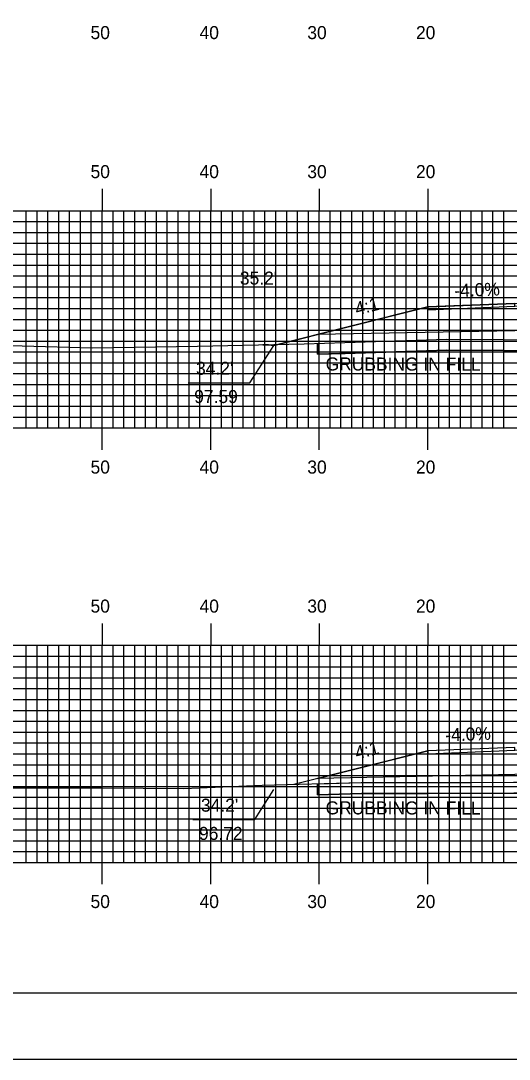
# Model space of a CAD drawing. Extents: x 1778712 to 1779055, y 442591 to 442811.
# Drawn here: x 1778820.3 to 1778865.3, y 442590.5 to 442686.2 of the extents above; entities that cross this region are included whole.
import ezdxf

# ---------------------------------------------------------------- set-up
doc = ezdxf.new("R2010")
doc.units = 0
for name, color, linetype in [('ANNOTATION', 7, 'Continuous'), ('BORDER', 7, 'Continuous'), ('D_Roadway_Centerline', 7, 'Continuous'), ('D_Roadway_Edge_Shoulder', 7, 'Continuous'), ('D_Roadway_SlopeLines', 7, 'Continuous'), ('D_Roadway_SubGrade', 7, 'Continuous'), ('D_Text_Standard', 7, 'Continuous'), ('GRUBBING IN FILL', 7, 'Continuous'), ('H_V ANNOTATION', 7, 'Continuous'), ('MAJOR', 7, 'Continuous'), ('MINOR', 7, 'Continuous'), ('PLOT BOUNDARY', 7, 'Continuous'), ('S_Roadway_Centerline', 7, 'Continuous')]:
    doc.layers.add(name, color=color, linetype=linetype)

msp = doc.modelspace()

# ---------------------------------------------------------------- linework, layer by layer
at = {"layer": 'ANNOTATION'}
for points in [[(1778835.728, 442652.833), (1778841.42, 442652.833), (1778843.642, 442656.259)], [(1778836.183, 442612.611), (1778841.875, 442612.611), (1778843.616, 442615.385)]]:
    msp.add_lwpolyline(points, dxfattribs=at)
at = {"layer": 'BORDER'}
msp.add_lwpolyline([(1778728.216, 442596.665), (1779048.216, 442596.665), (1779048.216, 442806.665), (1778728.216, 442806.665)], close=True, dxfattribs=at)
at = {"layer": 'D_Roadway_Centerline'}
msp.add_lwpolyline([(1778842.631, 442656.331), (1778842.722, 442656.331), (1778842.883, 442656.331), (1778843.136, 442656.319), (1778843.376, 442656.296), (1778843.389, 442656.295), (1778843.41, 442656.292), (1778843.642, 442656.259), (1778846.32, 442656.929), (1778847.642, 442657.259), (1778857.816, 442659.802), (1778859.485, 442659.869), (1778865.816, 442660.122), (1778877.816, 442660.362), (1778881.804, 442660.282), (1778889.816, 442660.122), (1778903.149, 442659.589), (1778912.858, 442657.162), (1778916.47, 442656.259)], dxfattribs=at)
at = {"layer": 'D_Roadway_Edge_Shoulder'}
for points in [[(1778865.816, 442660.122), (1778857.816, 442659.802), (1778857.816, 442659.552), (1778865.816, 442659.872)], [(1778865.816, 442619.247), (1778857.816, 442618.927), (1778857.816, 442618.677), (1778865.816, 442618.997)]]:
    msp.add_lwpolyline(points, close=True, dxfattribs=at)
at = {"layer": 'D_Roadway_SlopeLines'}
for points in [[(1778857.816, 442659.802), (1778843.642, 442656.259)], [(1778843.642, 442656.259), (1778843.389, 442656.295), (1778843.136, 442656.319), (1778842.883, 442656.331), (1778842.631, 442656.331)], [(1778857.816, 442618.927), (1778845.478, 442615.843)]]:
    msp.add_lwpolyline(points, dxfattribs=at)
at = {"layer": 'D_Roadway_SubGrade'}
for points in [[(1778865.816, 442657.622), (1778847.642, 442657.259), (1778857.816, 442659.802), (1778857.816, 442659.552), (1778865.816, 442659.872), (1778877.816, 442660.112), (1778889.816, 442659.872), (1778903.149, 442659.339), (1778903.149, 442659.589), (1778912.858, 442657.162), (1778889.816, 442657.622), (1778877.816, 442657.862)], [(1778865.816, 442616.747), (1778847.642, 442616.384), (1778857.816, 442618.927), (1778857.816, 442618.677), (1778865.816, 442618.997), (1778877.816, 442619.237), (1778889.816, 442618.997), (1778899.816, 442618.597), (1778899.816, 442618.847), (1778909.815, 442616.348), (1778889.816, 442616.747), (1778877.816, 442616.987)]]:
    msp.add_lwpolyline(points, close=True, dxfattribs=at)
at = {"layer": 'GRUBBING IN FILL'}
for p, q in [((1778847.642, 442656.456), (1778847.642, 442655.456)), ((1778847.642, 442656.456), (1778847.642, 442655.456)), ((1778847.642, 442615.902), (1778847.642, 442614.901)), ((1778847.642, 442615.902), (1778847.642, 442614.901))]:
    msp.add_line(p, q, dxfattribs=at)
for points in [[(1778847.642, 442656.456), (1778848.306, 442656.475), (1778850.185, 442656.529), (1778854.875, 442656.682), (1778859.566, 442656.834), (1778864.784, 442656.8), (1778870.002, 442656.765), (1778872.983, 442656.777), (1778877.816, 442656.845), (1778877.816, 442655.845), (1778872.992, 442655.777), (1778870.001, 442655.765), (1778864.79, 442655.8), (1778859.579, 442655.834), (1778854.897, 442655.682), (1778847.642, 442655.456)], [(1778847.642, 442656.456), (1778848.306, 442656.475), (1778850.185, 442656.529), (1778854.875, 442656.682), (1778859.566, 442656.834), (1778864.784, 442656.8), (1778870.002, 442656.765), (1778872.983, 442656.777), (1778877.816, 442656.845), (1778877.816, 442655.845), (1778872.992, 442655.777), (1778870.001, 442655.765), (1778864.79, 442655.8), (1778859.579, 442655.834), (1778854.897, 442655.682), (1778847.642, 442655.456)], [(1778847.642, 442614.901), (1778847.642, 442615.902), (1778851.685, 442616.011), (1778854.763, 442616.015), (1778861.781, 442616.033), (1778868.104, 442616.05), (1778874.6, 442616.221), (1778877.816, 442616.334), (1778877.816, 442615.333), (1778874.638, 442615.222), (1778870.508, 442615.053), (1778865.724, 442615.048), (1778857.843, 442615.018), (1778851.699, 442615.011)], [(1778847.642, 442614.901), (1778847.642, 442615.902), (1778851.685, 442616.011), (1778854.763, 442616.015), (1778861.781, 442616.033), (1778868.104, 442616.05), (1778874.6, 442616.221), (1778877.816, 442616.334), (1778877.816, 442615.333), (1778874.638, 442615.222), (1778870.508, 442615.053), (1778865.724, 442615.048), (1778857.843, 442615.018), (1778851.699, 442615.011)]]:
    msp.add_lwpolyline(points, close=True, dxfattribs=at)
for points in [[(1778847.642, 442655.456), (1778850.215, 442655.53), (1778859.579, 442655.834), (1778870.001, 442655.765), (1778872.992, 442655.777), (1778882.925, 442655.917), (1778895.028, 442656.037), (1778895.082, 442656.036), (1778895.146, 442656.035), (1778906.02, 442655.886), (1778907.99, 442655.97)], [(1778847.642, 442655.456), (1778850.215, 442655.53), (1778859.579, 442655.834), (1778870.001, 442655.765), (1778872.992, 442655.777), (1778882.925, 442655.917), (1778895.028, 442656.037), (1778895.082, 442656.036), (1778895.146, 442656.035), (1778906.02, 442655.886), (1778907.99, 442655.97)], [(1778847.642, 442614.901), (1778851.699, 442615.011), (1778857.843, 442615.018), (1778865.724, 442615.048), (1778870.508, 442615.053), (1778874.638, 442615.222), (1778882.441, 442615.495), (1778890.211, 442615.311), (1778897.213, 442615.21), (1778905.126, 442615.323), (1778907.99, 442615.371)], [(1778847.642, 442614.901), (1778851.699, 442615.011), (1778857.843, 442615.018), (1778865.724, 442615.048), (1778870.508, 442615.053), (1778874.638, 442615.222), (1778882.441, 442615.495), (1778890.211, 442615.311), (1778897.213, 442615.21), (1778905.126, 442615.323), (1778907.99, 442615.371)]]:
    msp.add_lwpolyline(points, dxfattribs=at)
at = {"layer": 'MAJOR'}
for p, q in [((1778827.816, 442670.669), (1778827.816, 442668.665)), ((1778837.816, 442670.669), (1778837.816, 442668.665)), ((1778847.816, 442670.669), (1778847.816, 442668.665)), ((1778857.816, 442670.669), (1778857.816, 442668.665)), ((1778737.816, 442668.665), (1779017.816, 442668.665)), ((1778737.816, 442668.665), (1779017.816, 442668.665)), ((1778827.816, 442648.665), (1778827.816, 442668.665)), ((1778837.816, 442648.665), (1778837.816, 442668.665)), ((1778847.816, 442648.665), (1778847.816, 442668.665)), ((1778857.816, 442648.665), (1778857.816, 442668.665)), ((1778737.816, 442663.665), (1779017.816, 442663.665)), ((1778737.816, 442658.665), (1779017.816, 442658.665)), ((1778737.816, 442653.665), (1779017.816, 442653.665)), ((1778737.816, 442648.665), (1779017.816, 442648.665)), ((1778737.816, 442648.665), (1779017.816, 442648.665)), ((1778827.816, 442646.661), (1778827.816, 442648.665)), ((1778837.816, 442646.661), (1778837.816, 442648.665)), ((1778847.816, 442646.661), (1778847.816, 442648.665)), ((1778857.816, 442646.661), (1778857.816, 442648.665)), ((1778827.816, 442630.669), (1778827.816, 442628.665)), ((1778837.816, 442630.669), (1778837.816, 442628.665)), ((1778847.816, 442630.669), (1778847.816, 442628.665)), ((1778857.816, 442630.669), (1778857.816, 442628.665)), ((1778737.816, 442628.665), (1779017.816, 442628.665)), ((1778737.816, 442628.665), (1779017.816, 442628.665)), ((1778827.816, 442608.665), (1778827.816, 442628.665)), ((1778837.816, 442608.665), (1778837.816, 442628.665)), ((1778847.816, 442608.665), (1778847.816, 442628.665)), ((1778857.816, 442608.665), (1778857.816, 442628.665)), ((1778737.816, 442623.665), (1779017.816, 442623.665)), ((1778737.816, 442618.665), (1779017.816, 442618.665)), ((1778737.816, 442613.665), (1779017.816, 442613.665)), ((1778737.816, 442608.665), (1779017.816, 442608.665)), ((1778737.816, 442608.665), (1779017.816, 442608.665)), ((1778827.816, 442606.661), (1778827.816, 442608.665)), ((1778837.816, 442606.661), (1778837.816, 442608.665)), ((1778847.816, 442606.661), (1778847.816, 442608.665)), ((1778857.816, 442606.661), (1778857.816, 442608.665))]:
    msp.add_line(p, q, dxfattribs=at)
at = {"layer": 'MINOR'}
for p, q in [((1778820.816, 442648.665), (1778820.816, 442668.665)), ((1778821.816, 442648.665), (1778821.816, 442668.665)), ((1778822.816, 442648.665), (1778822.816, 442668.665)), ((1778823.816, 442648.665), (1778823.816, 442668.665)), ((1778824.816, 442648.665), (1778824.816, 442668.665)), ((1778825.816, 442648.665), (1778825.816, 442668.665)), ((1778826.816, 442648.665), (1778826.816, 442668.665)), ((1778828.816, 442648.665), (1778828.816, 442668.665)), ((1778829.816, 442648.665), (1778829.816, 442668.665)), ((1778830.816, 442648.665), (1778830.816, 442668.665)), ((1778831.816, 442648.665), (1778831.816, 442668.665)), ((1778832.816, 442648.665), (1778832.816, 442668.665)), ((1778833.816, 442648.665), (1778833.816, 442668.665)), ((1778834.816, 442648.665), (1778834.816, 442668.665)), ((1778835.816, 442648.665), (1778835.816, 442668.665)), ((1778836.816, 442648.665), (1778836.816, 442668.665)), ((1778838.816, 442648.665), (1778838.816, 442668.665)), ((1778839.816, 442648.665), (1778839.816, 442668.665)), ((1778840.816, 442648.665), (1778840.816, 442668.665)), ((1778841.816, 442648.665), (1778841.816, 442668.665)), ((1778842.816, 442648.665), (1778842.816, 442668.665)), ((1778843.816, 442648.665), (1778843.816, 442668.665)), ((1778844.816, 442648.665), (1778844.816, 442668.665)), ((1778845.816, 442648.665), (1778845.816, 442668.665)), ((1778846.816, 442648.665), (1778846.816, 442668.665)), ((1778848.816, 442648.665), (1778848.816, 442668.665)), ((1778849.816, 442648.665), (1778849.816, 442668.665)), ((1778850.816, 442648.665), (1778850.816, 442668.665)), ((1778851.816, 442648.665), (1778851.816, 442668.665)), ((1778852.816, 442648.665), (1778852.816, 442668.665)), ((1778853.816, 442648.665), (1778853.816, 442668.665)), ((1778854.816, 442648.665), (1778854.816, 442668.665)), ((1778855.816, 442648.665), (1778855.816, 442668.665)), ((1778856.816, 442648.665), (1778856.816, 442668.665)), ((1778858.816, 442648.665), (1778858.816, 442668.665)), ((1778859.816, 442648.665), (1778859.816, 442668.665)), ((1778860.816, 442648.665), (1778860.816, 442668.665)), ((1778861.816, 442648.665), (1778861.816, 442668.665)), ((1778862.816, 442648.665), (1778862.816, 442668.665)), ((1778863.816, 442648.665), (1778863.816, 442668.665)), ((1778864.816, 442648.665), (1778864.816, 442668.665)), ((1778737.816, 442667.665), (1779017.816, 442667.665)), ((1778737.816, 442666.665), (1779017.816, 442666.665)), ((1778737.816, 442665.665), (1779017.816, 442665.665)), ((1778737.816, 442664.665), (1779017.816, 442664.665)), ((1778737.816, 442662.665), (1779017.816, 442662.665)), ((1778737.816, 442661.665), (1779017.816, 442661.665)), ((1778737.816, 442660.665), (1779017.816, 442660.665)), ((1778737.816, 442659.665), (1779017.816, 442659.665)), ((1778737.816, 442657.665), (1779017.816, 442657.665)), ((1778737.816, 442656.665), (1779017.816, 442656.665)), ((1778737.816, 442655.665), (1779017.816, 442655.665)), ((1778737.816, 442654.665), (1779017.816, 442654.665)), ((1778737.816, 442652.665), (1779017.816, 442652.665)), ((1778737.816, 442651.665), (1779017.816, 442651.665)), ((1778737.816, 442650.665), (1779017.816, 442650.665)), ((1778737.816, 442649.665), (1779017.816, 442649.665)), ((1778820.816, 442608.665), (1778820.816, 442628.665)), ((1778821.816, 442608.665), (1778821.816, 442628.665)), ((1778822.816, 442608.665), (1778822.816, 442628.665)), ((1778823.816, 442608.665), (1778823.816, 442628.665)), ((1778824.816, 442608.665), (1778824.816, 442628.665)), ((1778825.816, 442608.665), (1778825.816, 442628.665)), ((1778826.816, 442608.665), (1778826.816, 442628.665)), ((1778828.816, 442608.665), (1778828.816, 442628.665)), ((1778829.816, 442608.665), (1778829.816, 442628.665)), ((1778830.816, 442608.665), (1778830.816, 442628.665)), ((1778831.816, 442608.665), (1778831.816, 442628.665)), ((1778832.816, 442608.665), (1778832.816, 442628.665)), ((1778833.816, 442608.665), (1778833.816, 442628.665)), ((1778834.816, 442608.665), (1778834.816, 442628.665)), ((1778835.816, 442608.665), (1778835.816, 442628.665)), ((1778836.816, 442608.665), (1778836.816, 442628.665)), ((1778838.816, 442608.665), (1778838.816, 442628.665)), ((1778839.816, 442608.665), (1778839.816, 442628.665)), ((1778840.816, 442608.665), (1778840.816, 442628.665)), ((1778841.816, 442608.665), (1778841.816, 442628.665)), ((1778842.816, 442608.665), (1778842.816, 442628.665)), ((1778843.816, 442608.665), (1778843.816, 442628.665)), ((1778844.816, 442608.665), (1778844.816, 442628.665)), ((1778845.816, 442608.665), (1778845.816, 442628.665)), ((1778846.816, 442608.665), (1778846.816, 442628.665)), ((1778848.816, 442608.665), (1778848.816, 442628.665)), ((1778849.816, 442608.665), (1778849.816, 442628.665)), ((1778850.816, 442608.665), (1778850.816, 442628.665)), ((1778851.816, 442608.665), (1778851.816, 442628.665)), ((1778852.816, 442608.665), (1778852.816, 442628.665)), ((1778853.816, 442608.665), (1778853.816, 442628.665)), ((1778854.816, 442608.665), (1778854.816, 442628.665)), ((1778855.816, 442608.665), (1778855.816, 442628.665)), ((1778856.816, 442608.665), (1778856.816, 442628.665)), ((1778858.816, 442608.665), (1778858.816, 442628.665)), ((1778859.816, 442608.665), (1778859.816, 442628.665)), ((1778860.816, 442608.665), (1778860.816, 442628.665)), ((1778861.816, 442608.665), (1778861.816, 442628.665)), ((1778862.816, 442608.665), (1778862.816, 442628.665)), ((1778863.816, 442608.665), (1778863.816, 442628.665)), ((1778864.816, 442608.665), (1778864.816, 442628.665)), ((1778737.816, 442627.665), (1779017.816, 442627.665)), ((1778737.816, 442626.665), (1779017.816, 442626.665)), ((1778737.816, 442625.665), (1779017.816, 442625.665)), ((1778737.816, 442624.665), (1779017.816, 442624.665)), ((1778737.816, 442622.665), (1779017.816, 442622.665)), ((1778737.816, 442621.665), (1779017.816, 442621.665)), ((1778737.816, 442620.665), (1779017.816, 442620.665)), ((1778737.816, 442619.665), (1779017.816, 442619.665)), ((1778737.816, 442617.665), (1779017.816, 442617.665)), ((1778737.816, 442616.665), (1779017.816, 442616.665)), ((1778737.816, 442615.665), (1779017.816, 442615.665)), ((1778737.816, 442614.665), (1779017.816, 442614.665)), ((1778737.816, 442612.665), (1779017.816, 442612.665)), ((1778737.816, 442611.665), (1779017.816, 442611.665)), ((1778737.816, 442610.665), (1779017.816, 442610.665)), ((1778737.816, 442609.665), (1779017.816, 442609.665))]:
    msp.add_line(p, q, dxfattribs=at)
at = {"layer": 'PLOT BOUNDARY'}
msp.add_lwpolyline([(1778712.029, 442590.547), (1779052.029, 442590.547), (1779052.029, 442810.547), (1778712.029, 442810.547)], close=True, dxfattribs=at)
at = {"layer": 'S_Roadway_Centerline'}
for points in [[(1778813.946, 442656.402), (1778826.915, 442656.052), (1778836.598, 442656.188), (1778846.427, 442656.422), (1778850.185, 442656.529), (1778859.566, 442656.834), (1778870.002, 442656.765), (1778872.983, 442656.777), (1778882.913, 442656.917), (1778895.029, 442657.037), (1778895.093, 442657.036), (1778895.158, 442657.035), (1778906.006, 442656.886), (1778917.727, 442657.387), (1778918.527, 442657.421), (1778919.257, 442657.428), (1778929.36, 442657.357), (1778940.033, 442657.27)], [(1778817.437, 442615.533), (1778827.835, 442615.539), (1778835.333, 442615.477), (1778842.558, 442615.764), (1778851.685, 442616.011), (1778857.84, 442616.018), (1778865.721, 442616.048), (1778870.487, 442616.053), (1778874.6, 442616.221), (1778882.435, 442616.495), (1778890.23, 442616.31), (1778897.213, 442616.21), (1778905.11, 442616.322), (1778915.021, 442616.491), (1778918.005, 442616.612), (1778920.68, 442616.594), (1778937.869, 442616.835)]]:
    msp.add_lwpolyline(points, dxfattribs=at)

# ---------------------------------------------------------------- texts
at = {"layer": 'ANNOTATION'}
for s, rotation, p in [('-4.0%', 2.29074, (1778860.282, 442660.702)), ('4:1', 14.0329, (1778851.265, 442659.026)), ('-4.0%', 2.29073, (1778859.448, 442619.794)), ('4:1', 14.0329, (1778851.265, 442618.151))]:
    msp.add_text(s, height=1.2, rotation=rotation, dxfattribs=at).set_placement(p)
for s, p in [("34.2'", (1778836.463, 442653.559)), ('97.59', (1778836.296, 442650.959)), ("34.2'", (1778836.918, 442613.337)), ('96.72', (1778836.736, 442610.737))]:
    msp.add_text(s, height=1.2, dxfattribs=at).set_placement(p)
at = {"layer": 'D_Text_Standard'}
msp.add_text("35.2'", height=1.2, dxfattribs=at).set_placement((1778840.504, 442661.862))
at = {"layer": 'GRUBBING IN FILL'}
for p in [(1778848.401, 442653.958), (1778848.401, 442613.09)]:
    msp.add_text('GRUBBING IN FILL', height=1.2, rotation=359.9351, dxfattribs=at).set_placement(p)
at = {"layer": 'H_V ANNOTATION'}
for s, p in [('50', (1778826.745, 442684.465)), ('40', (1778836.788, 442684.465)), ('30', (1778846.713, 442684.465)), ('20', (1778856.724, 442684.465)), ('50', (1778826.745, 442671.665)), ('40', (1778836.788, 442671.665)), ('30', (1778846.713, 442671.665)), ('20', (1778856.724, 442671.665)), ('50', (1778826.745, 442644.465)), ('40', (1778836.788, 442644.465)), ('30', (1778846.713, 442644.465)), ('20', (1778856.724, 442644.465)), ('50', (1778826.745, 442631.665)), ('40', (1778836.788, 442631.665)), ('30', (1778846.713, 442631.665)), ('20', (1778856.724, 442631.665)), ('50', (1778826.745, 442604.465)), ('40', (1778836.788, 442604.465)), ('30', (1778846.713, 442604.465)), ('20', (1778856.724, 442604.465))]:
    msp.add_text(s, height=1.2, dxfattribs=at).set_placement(p)

doc.saveas('drawing.dxf')
